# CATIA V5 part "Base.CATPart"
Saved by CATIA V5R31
Part number: Part1
Bounding box of the stored display mesh (mm): x -50 to 50, y -25 to 25, z 0 to 50
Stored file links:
  D:\PROJECTS\Project 2021\US EDITION\CATIA V5 6R 2021\Resources\Part Files\c12_catia_v5_6r2021_prt\c12_catia_v5-6r2021 figr_12-15\Base.CATPart
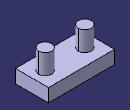
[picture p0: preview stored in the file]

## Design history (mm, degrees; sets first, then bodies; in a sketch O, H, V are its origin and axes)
Body1 (main body)
  Sketch1 on xy-plane, origin (0, 0, 0), H (1, 0, 0), V (0, 1, 0)
    line L1 (50, 25) -> (50, -25)
    line L2 (50, -25) -> (-50, -25)
    line L3 (-50, -25) -> (-50, 25)
    line L4 (-50, 25) -> (50, 25)
    circle A1 centre (-30, 0) radius 10
    point P5 (-30, 0)
    circle A2 centre (30, 0) radius 10
    length L2 = 100
    length L1 = 50
    radius A1 = 10
    distance P5 V = 30
    vertical: L1 V, L3 V
    horizontal: L2 H, L4 H
    equidistance: L1 L3 O, L2 L4 O
    coincidence: P5 H
    symmetry: A1 A2 V
  MultiPad1: profile Sketch1, domains (length 20; length 50; length 50)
